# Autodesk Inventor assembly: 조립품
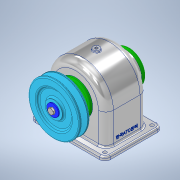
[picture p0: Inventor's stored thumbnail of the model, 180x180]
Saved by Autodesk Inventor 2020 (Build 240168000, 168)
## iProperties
Created: 2022-09
Part Number: 조립품
Document SubType Name: Assembly
Designer: Administrator
Author: Administrator
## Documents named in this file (16)
- C:\Users\Administrator\Pictures\Desktop\720906V1015\조립품.iam
- C:\Users\Administrator\Pictures\Desktop\720906V1015\본체.ipt
- C:\Users\Administrator\Pictures\Desktop\720906V1015\V-벨트풀리.ipt
- C:\Users\Administrator\Pictures\Desktop\720906V1015\뒤커버.ipt
- C:\Users\Administrator\Pictures\Desktop\720906V1015\멈춤나사 M4 x 10.ipt
- C:\Users\Administrator\Pictures\Desktop\720906V1015\베어링 6203.ipt
- C:\Users\Administrator\Pictures\Desktop\720906V1015\볼트 M3 x 10.ipt
- C:\Users\Administrator\Pictures\Desktop\720906V1015\스퍼기어.ipt
- C:\Users\Administrator\Pictures\Desktop\720906V1015\앞커버.ipt
- C:\Users\Administrator\Pictures\Desktop\720906V1015\오일 실 17 x 30 x 8.ipt
- C:\Users\Administrator\Pictures\Desktop\720906V1015\와셔 6 x 22.ipt
- C:\Users\Administrator\Pictures\Desktop\720906V1015\육각머리볼트 M3 x 8.ipt
- C:\Users\Administrator\Pictures\Desktop\720906V1015\축.ipt
- C:\Users\Administrator\Pictures\Desktop\720906V1015\칼라.ipt
- C:\Users\Administrator\Pictures\Desktop\720906V1015\키 5 x 5 x 18.ipt
- C:\Users\Administrator\Pictures\Desktop\720906V1015\키 6 x 6 x 22.ipt
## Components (9 placed, 2 different names)
1. V-벨트풀리:1 — 각도:3
2. ISO 4762 M3 x 10:1
3. ISO 4762 M3 x 10:2
4. ISO 4762 M3 x 10:3
5. ISO 4762 M3 x 10:4
6. ISO 4762 M3 x 10:5
7. ISO 4762 M3 x 10:6
8. ISO 4762 M3 x 10:7
9. ISO 4762 M3 x 10:8
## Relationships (1: Angle 1)
- 각도:3 [Angle]: V-벨트풀리:1
